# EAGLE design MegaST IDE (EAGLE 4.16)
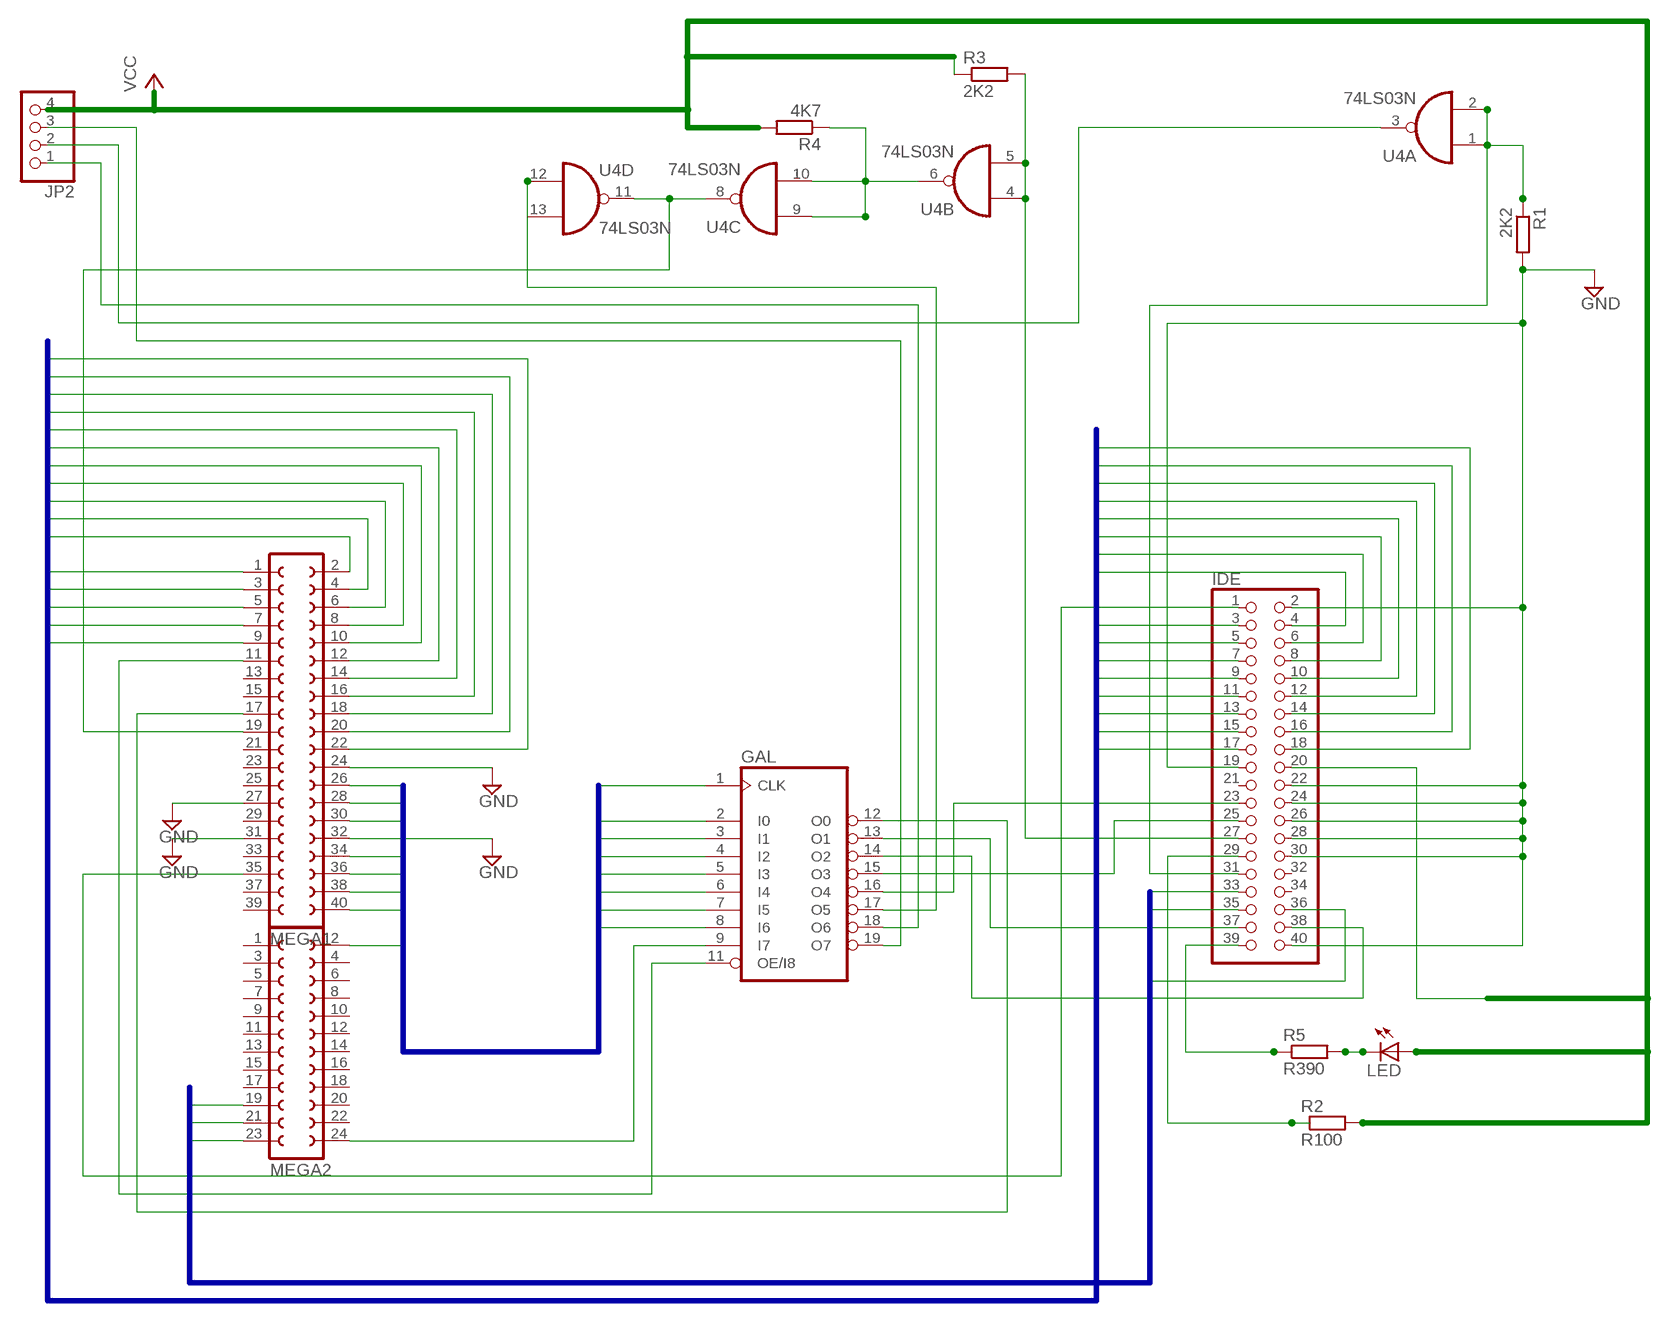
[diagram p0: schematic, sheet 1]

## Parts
GAL  16V8  [DIL20]
IDE  PINHD-2X20  [2X20]
JP2  PINHD-1X4  [1X04]
LED  LED3MM  [LED3MM]
MEGA1  FE20-2  [FE20-2]
MEGA2  FE12-2  [FE12-2]
R1  2K2  R-EU_0207/10  [0207/10]
R2  R100  R-EU_0207/10  [0207/10]
R3  2K2  R-EU_0207/10  [0207/10]
R4  4K7  R-EU_0207/10  [0207/10]
R5  R390  R-EU_0207/10  [0207/10]
U4  74LS03N  [DIL14]

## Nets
A2: IDE.35 MEGA2.19
A3: IDE.33 MEGA2.21
A4: IDE.36 MEGA2.23
A5: GAL.9(I7) MEGA2.24
A16: GAL.8(I6) MEGA2.2
A17: GAL.7(I5) MEGA1.40
A18: GAL.6(I4) MEGA1.38
A19: GAL.5(I3) MEGA1.36
A20: GAL.4(I2) MEGA1.34
A21: GAL.3(I1) MEGA1.30
A22: GAL.2(I0) MEGA1.28
A23: GAL.1(CLK) MEGA1.26
ACSI10: JP2.2 U4.3(A:O)
AS: GAL.11(OE/I8) MEGA1.11
CER: GAL.18(O6) JP2.1
D0: IDE.17 MEGA1.9
D1: IDE.15 MEGA1.7
D2: IDE.13 MEGA1.5
D3: IDE.11 MEGA1.3
D4: IDE.9 MEGA1.1
D5: IDE.7 MEGA1.2
D6: IDE.5 MEGA1.4
D7: IDE.3 MEGA1.6
D8: IDE.4 MEGA1.8
D9: IDE.6 MEGA1.10
D10: IDE.8 MEGA1.12
D11: IDE.10 MEGA1.14
D12: IDE.12 MEGA1.16
D13: IDE.14 MEGA1.18
D14: IDE.16 MEGA1.20
D15: IDE.18 MEGA1.22
DASP: IDE.39 R5.1
DMACK: IDE.29 R2.1
DTACK: MEGA1.19 U4.8(C:O) U4.11(D:O)
GND: IDE.2 IDE.19 IDE.22 IDE.24 IDE.26 IDE.28 IDE.30 IDE.40 MEGA1.24 MEGA1.27 MEGA1.31 MEGA1.32 R1.2
INTRQ: IDE.31 R1.1 U4.1(A:I0) U4.2(A:I1)
IORD: GAL.15(O3) IDE.25
IORDY: IDE.27 R3.2 U4.4(B:I0) U4.5(B:I1)
IOWR: GAL.16(O4) IDE.23
R5_LED: LED.K(C) R5.2
R/W: GAL.12(O0) MEGA1.17
RESET: IDE.1 MEGA1.35
ROM2: GAL.19(O7) JP2.3
SELP: GAL.13(O1) IDE.37
SELS: GAL.14(O2) IDE.38
U4_VCC1: R4.1 U4.6(B:O) U4.9(C:I0) U4.10(C:I1)
U4DTACK: GAL.17(O5) U4.12(D:I0) U4.13(D:I1)
VCC: IDE.20 JP2.4 LED.A R2.2 R3.1 R4.2
Unconnected: IDE.21 IDE.32 IDE.34 MEGA1.13 MEGA1.15 MEGA1.21 MEGA1.23 MEGA1.25 MEGA1.29 MEGA1.33 MEGA1.37 MEGA1.39 MEGA2.1 MEGA2.3 MEGA2.4 MEGA2.5 MEGA2.6 MEGA2.7 MEGA2.8 MEGA2.9 MEGA2.10 MEGA2.11 MEGA2.12 MEGA2.13 MEGA2.14 MEGA2.15 MEGA2.16 MEGA2.17 MEGA2.18 MEGA2.20 MEGA2.22

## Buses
A[16..23]
D[0..15]
A[2..4]

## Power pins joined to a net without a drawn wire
GND: GAL.10(GND) U4.7(P:GND)
VCC: GAL.20(VCC) U4.14(P:VCC)

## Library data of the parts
GAL = pal:16V8: PAL
IDE = pinhead:PINHD-2X20: PIN HEADER
JP2 = pinhead:PINHD-1X4: PIN HEADER
LED = led:LED: LED
MEGA1 = con-lsta:FE20-2: FEMALE HEADER
MEGA2 = con-lsta:FE12-2: FEMALE HEADER
R1-R5 = rcl:R-EU_: RESISTOR, European symbol
U4 = 74xx-eu:74*03: Quad 2-input NAND gate, open collector output

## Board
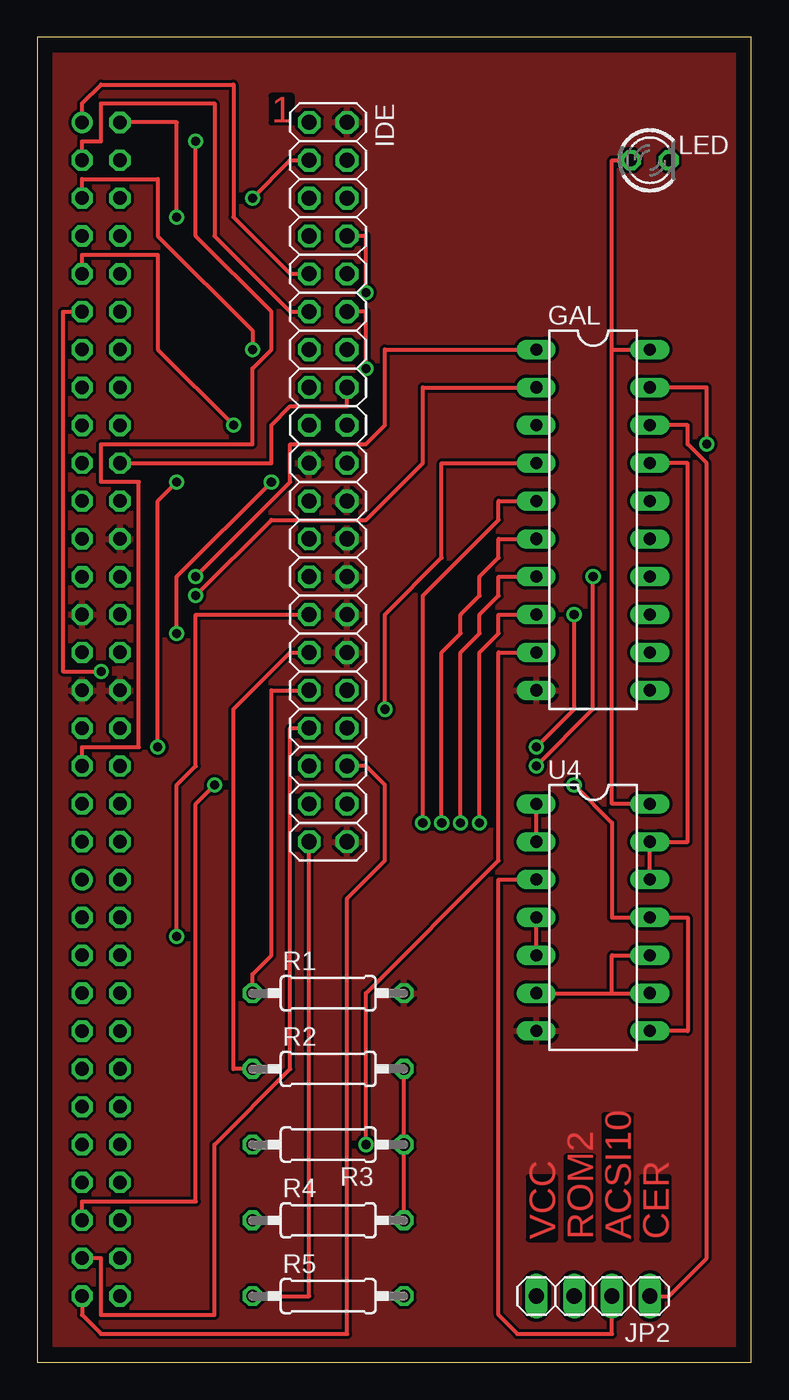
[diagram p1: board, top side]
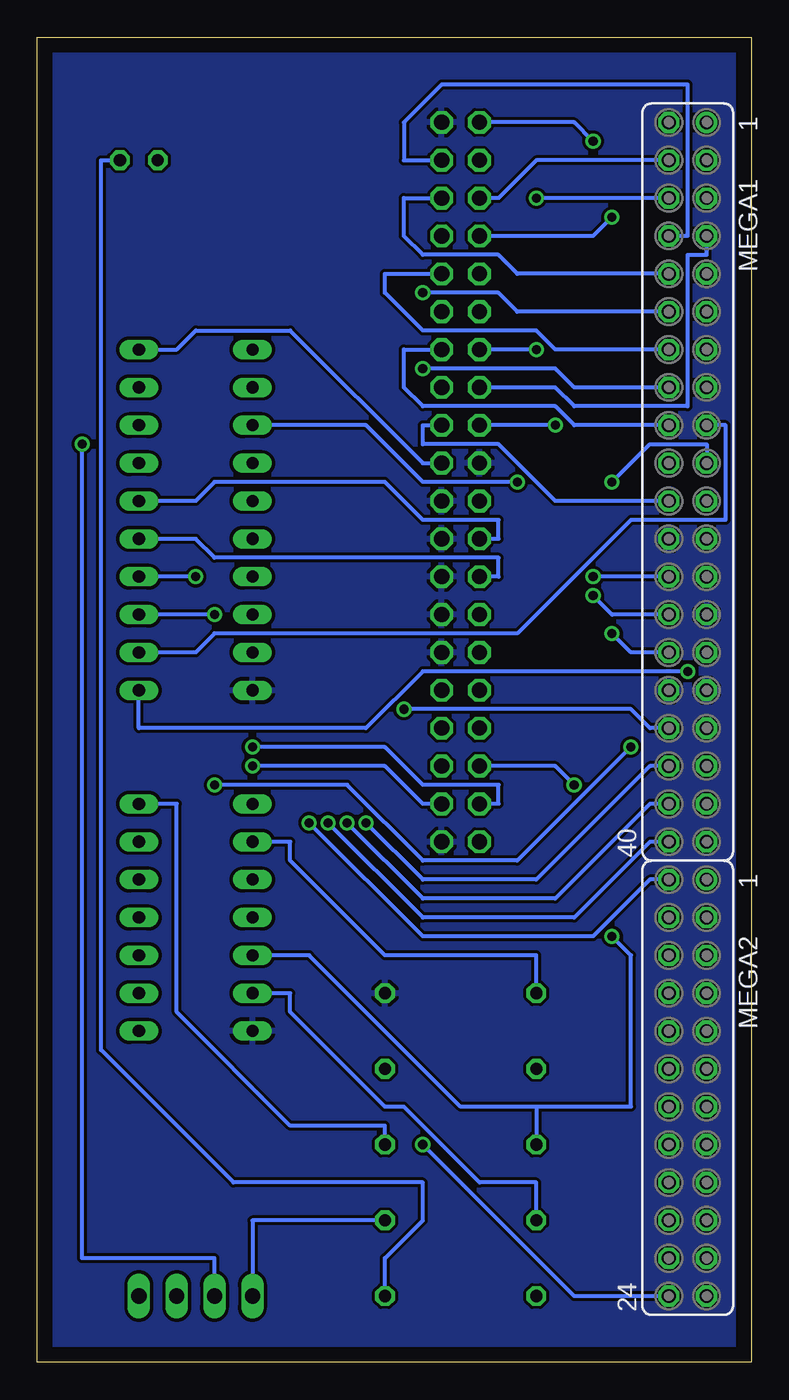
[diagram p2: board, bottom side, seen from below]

Size 47.93 x 88.89 mm. Coordinates in mm from the lower left corner, seen from the top.
Outline: 0,0 47.93,0 47.93,88.89 0,88.89 0,0
Copper layers (1*16): Top 0.035mm / dielectric 1.5mm / Bottom 0.035mm
Design rules "default": minimum track width 10mil, minimum drill 24mil, track to track 8mil, track to pad 8mil, pad to pad 8mil, via to via 8mil, smd to smd 8mil, copper to edge 40mil, drill to drill 8mil, minimum pad ring 10mil, minimum via ring 8mil, stop-mask expansion 4mil, vias tented up to drill 0mil, thermal gap 10mil

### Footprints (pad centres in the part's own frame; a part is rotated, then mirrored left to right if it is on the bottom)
DIL20 = drill 0.813 long: 1 -11.43,-3.81; 2 -8.89,-3.81; 3 -6.35,-3.81; 4 -3.81,-3.81; 5 -1.27,-3.81; 6 1.27,-3.81; 7 3.81,-3.81; 8 6.35,-3.81; 9 8.89,-3.81; 10 11.43,-3.81; 11 11.43,3.81; 12 8.89,3.81; 13 6.35,3.81; 14 3.81,3.81; 15 1.27,3.81; 16 -1.27,3.81; 17 -3.81,3.81; 18 -6.35,3.81; 19 -8.89,3.81; 20 -11.43,3.81
2X20 = drill 1.016 octagon: 1 -24.13,-1.27; 2 -24.13,1.27; 3 -21.59,-1.27; 4 -21.59,1.27; 5 -19.05,-1.27; 6 -19.05,1.27; 7 -16.51,-1.27; 8 -16.51,1.27; 9 -13.97,-1.27; 10 -13.97,1.27; 11 -11.43,-1.27; 12 -11.43,1.27; 13 -8.89,-1.27; 14 -8.89,1.27; 15 -6.35,-1.27; 16 -6.35,1.27; 17 -3.81,-1.27; 18 -3.81,1.27; 19 -1.27,-1.27; 20 -1.27,1.27; 21 1.27,-1.27; 22 1.27,1.27; 23 3.81,-1.27; 24 3.81,1.27; 25 6.35,-1.27; 26 6.35,1.27; 27 8.89,-1.27; 28 8.89,1.27; 29 11.43,-1.27; 30 11.43,1.27; 31 13.97,-1.27; 32 13.97,1.27; 33 16.51,-1.27; 34 16.51,1.27; 35 19.05,-1.27; 36 19.05,1.27; 37 21.59,-1.27; 38 21.59,1.27; 39 24.13,-1.27; 40 24.13,1.27
1X04 = drill 1.016 long: 1 -3.81,0; 2 -1.27,0; 3 1.27,0; 4 3.81,0
LED3MM = drill 0.813 octagon: A -1.27,0; K 1.27,0
FE20-2 = drill 0.914 round: 1 -24.13,1.27 | drill 0.914 octagon: 2 -24.13,-1.27; 3 -21.59,1.27; 4 -21.59,-1.27; 5 -19.05,1.27; 6 -19.05,-1.27; 7 -16.51,1.27; 8 -16.51,-1.27; 9 -13.97,1.27; 10 -13.97,-1.27; 11 -11.43,1.27; 12 -11.43,-1.27; 13 -8.89,1.27; 14 -8.89,-1.27; 15 -6.35,1.27; 16 -6.35,-1.27; 17 -3.81,1.27; 18 -3.81,-1.27; 19 -1.27,1.27; 20 -1.27,-1.27; 21 1.27,1.27; 22 1.27,-1.27; 23 3.81,1.27; 24 3.81,-1.27; 25 6.35,1.27; 26 6.35,-1.27; 27 8.89,1.27; 28 8.89,-1.27; 29 11.43,1.27; 30 11.43,-1.27; 31 13.97,1.27; 32 13.97,-1.27; 33 16.51,1.27; 34 16.51,-1.27; 35 19.05,1.27; 36 19.05,-1.27; 37 21.59,1.27; 38 21.59,-1.27; 39 24.13,1.27; 40 24.13,-1.27
FE12-2 = drill 0.914 round: 1 -13.97,1.27 | drill 0.914 octagon: 2 -13.97,-1.27; 3 -11.43,1.27; 4 -11.43,-1.27; 5 -8.89,1.27; 6 -8.89,-1.27; 7 -6.35,1.27; 8 -6.35,-1.27; 9 -3.81,1.27; 10 -3.81,-1.27; 11 -1.27,1.27; 12 -1.27,-1.27; 13 1.27,1.27; 14 1.27,-1.27; 15 3.81,1.27; 16 3.81,-1.27; 17 6.35,1.27; 18 6.35,-1.27; 19 8.89,1.27; 20 8.89,-1.27; 21 11.43,1.27; 22 11.43,-1.27; 23 13.97,1.27; 24 13.97,-1.27
0207/10 = drill 0.813 octagon: 1 -5.08,0; 2 5.08,0
DIL14 = drill 0.813 long: 1 -7.62,-3.81; 2 -5.08,-3.81; 3 -2.54,-3.81; 4 0,-3.81; 5 2.54,-3.81; 6 5.08,-3.81; 7 7.62,-3.81; 8 7.62,3.81; 9 5.08,3.81; 10 2.54,3.81; 11 0,3.81; 12 -2.54,3.81; 13 -5.08,3.81; 14 -7.62,3.81

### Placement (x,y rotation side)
GAL  37.3,56.51 270 top
IDE  19.52,59.05 270 top
JP2  37.3,4.44 180 top
LED  41.11,80.64 0 top
MEGA1  4.28,59.05 270 bottom
MEGA2  4.28,18.41 270 bottom
R1  19.52,24.76 0 top
R2  19.52,19.68 0 top
R3  19.52,14.6 180 top
R4  19.52,9.52 0 top
R5  19.52,4.44 0 top
U4  37.3,29.84 270 top

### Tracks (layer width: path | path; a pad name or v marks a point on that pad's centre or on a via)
A2  (via drill 0.61)
  Top 0.254: MEGA2.19 3.01,10.79 10.63,10.79 10.63,37.46 v11.9,38.73
  Bottom 0.254: v11.9,38.73 13.17,40 IDE.35
A3
  Top 0.254: MEGA2.21 4.28,6.98 4.28,3.17 11.9,3.17 11.9,14.6 16.98,19.68 16.98,42.54 IDE.33
A4
  Top 0.254: MEGA2.23 3.01,3.17 4.28,1.9 20.79,1.9 20.79,31.11 23.33,33.65 23.33,38.73 22.06,40 IDE.36
A5  (via drill 0.61)
  Top 0.254: v22.06,14.6 22.06,24.76 30.95,33.65 30.95,47.62 GAL.9
  Bottom 0.254: v22.06,14.6 11.9,4.44 MEGA2.24
A16  (via drill 0.61)
  Top 0.254: v29.68,36.19 29.68,47.62 30.95,48.89 30.95,50.16 GAL.8
  Bottom 0.254: v29.68,36.19 22.06,28.57 10.63,28.57 6.82,32.38 MEGA2.2
A17  (via drill 0.61)
  Top 0.254: v28.41,36.19 28.41,47.62 29.68,48.89 29.68,50.16 30.95,51.43 30.95,52.7 GAL.7
  Bottom 0.254: v28.41,36.19 22.06,29.84 11.9,29.84 6.82,34.92 MEGA1.40
A18  (via drill 0.61)
  Top 0.254: v27.14,36.19 27.14,47.62 28.41,48.89 28.41,50.16 29.68,51.43 29.68,52.7 30.95,53.97 30.95,55.24 GAL.6
  Bottom 0.254: v27.14,36.19 22.06,31.11 13.17,31.11 6.82,37.46 MEGA1.38
A19  (via drill 0.61)
  Top 0.254: v25.87,36.19 25.87,51.43 30.95,56.51 30.95,57.78 GAL.5
  Bottom 0.254: v25.87,36.19 22.06,32.38 14.44,32.38 6.82,40 MEGA1.36
A20  (via drill 0.61)
  Top 0.254: v23.33,43.81 23.33,50.16 27.14,53.97 27.14,60.32 GAL.4
  Bottom 0.254: v23.33,43.81 8.09,43.81 6.82,42.54 MEGA1.34
A21  (via drill 0.61)
  Top 0.254: v15.71,59.05 9.36,52.7 v9.36,48.89
  Bottom 0.254: v15.71,59.05 22.06,59.05 25.87,62.86 GAL.3 | v9.36,48.89 8.09,47.62 MEGA1.30
A22  (via drill 0.61)
  Top 0.254: v10.63,51.43 15.71,56.51 22.06,56.51 25.87,60.32 25.87,65.4 GAL.2
  Bottom 0.254: v10.63,51.43 9.36,50.16 MEGA1.28
A23  (via drill 0.61)
  Top 0.254: v10.63,52.7 16.98,59.05 16.98,61.59 22.06,61.59 23.33,62.86 23.33,67.94 GAL.1
  Bottom 0.254: MEGA1.26 v10.63,52.7
ACSI10
  Top 0.254: U4.3 30.95,32.38 30.95,3.17 32.22,1.9 38.57,1.9 JP2.2
AS  (via drill 0.61)
  Top 0.254: v4.28,46.35 1.74,46.35 1.74,70.48 MEGA1.11
  Bottom 0.254: GAL.11 41.11,42.54 25.87,42.54 22.06,46.35 v4.28,46.35
CER
  Top 0.254: JP2.1 42.38,4.44 44.92,6.98 44.92,60.32 43.65,61.59 43.65,62.86 GAL.18
D0  (via drill 0.61)
  Top 0.254: MEGA1.9 3.01,74.29 8.09,74.29 8.09,67.94 v13.17,62.86
  Bottom 0.254: v13.17,62.86 IDE.17
D1
  Bottom 0.254: MEGA1.7 3.01,74.29 4.28,74.29 4.28,64.13 11.9,64.13 13.17,65.4 IDE.15
D2  (via drill 0.61)
  Top 0.254: MEGA1.5 3.01,79.37 8.09,79.37 8.09,75.56 14.44,69.21 v14.44,67.94
  Bottom 0.254: v14.44,67.94 IDE.13
D3
  Top 0.254: MEGA1.3 3.01,81.91 4.28,81.91 4.28,84.45 11.9,84.45 11.9,75.56 16.98,70.48 IDE.11
D4
  Top 0.254: MEGA1.1 3.01,84.45 4.28,85.72 13.17,85.72 13.17,76.83 16.98,73.02 IDE.9
D5  (via drill 0.61)
  Top 0.254: MEGA1.2 9.36,83.18 v9.36,76.83
  Bottom 0.254: v9.36,76.83 10.63,75.56 IDE.7
D6
  Bottom 0.254: MEGA1.4 14.44,80.64 16.98,78.1 IDE.5
D7  (via drill 0.61)
  Top 0.254: v14.44,78.1 16.98,80.64 IDE.3
  Bottom 0.254: MEGA1.6 v14.44,78.1
D8
  Bottom 0.254: MEGA1.8 4.28,75.56 4.28,85.72 20.79,85.72 23.33,83.18 23.33,80.64 IDE.4
D9
  Bottom 0.254: MEGA1.10 15.71,73.02 16.98,74.29 22.06,74.29 23.33,75.56 23.33,78.1 IDE.6
D10  (via drill 0.61)
  Top 0.254: v22.06,71.75 22.06,75.56 IDE.8
  Bottom 0.254: MEGA1.12 15.71,70.48 16.98,71.75 v22.06,71.75
D11
  Bottom 0.254: MEGA1.14 13.17,67.94 14.44,69.21 22.06,69.21 24.6,71.75 24.6,73.02 IDE.10
D12  (via drill 0.61)
  Top 0.254: v22.06,66.67 22.06,70.48 IDE.12
  Bottom 0.254: MEGA1.16 11.9,65.4 13.17,66.67 v22.06,66.67
D13
  Bottom 0.254: MEGA1.18 11.9,62.86 13.17,64.13 22.06,64.13 23.33,65.4 23.33,67.94 IDE.14
D14
  Top 0.254: MEGA1.20 15.71,60.32 15.71,62.86 16.98,64.13 20.79,64.13 IDE.16
D15
  Bottom 0.254: MEGA1.22 13.17,57.78 16.98,61.59 22.06,61.59 22.06,62.86 IDE.18
DASP
  Top 0.254: R5.1 18.25,4.44 IDE.39
DMACK
  Top 0.254: R2.1 13.17,19.68 13.17,43.81 16.98,47.62 IDE.29
DTACK  (via drill 0.61)
  Top 0.254: U4.8 43.65,22.22 43.65,29.84 U4.11 38.57,29.84 38.57,36.19 v36.03,38.73 | v9.36,59.05 8.09,57.78 v8.09,41.27
  Bottom 0.254: MEGA1.19 3.01,61.59 6.82,61.59 v9.36,59.05 | v8.09,41.27 15.71,33.65 22.06,33.65 27.14,38.73 v36.03,38.73
GND
  pour Bottom: -0.8,88.26 48.73,88.26 48.73,0.63 -0.8,0.63
  pour Top: -0.8,88.26 48.73,88.26 48.73,0.63 -0.8,0.63
INTRQ
  Top 0.254: U4.2 U4.1 | IDE.31 15.71,45.08 15.71,27.3 14.44,26.03 R1.1
  Bottom 0.254: R1.1 14.44,27.3 24.6,27.3 30.95,33.65 30.95,34.92 U4.2
IORD
  Bottom 0.254: IDE.25 16.98,52.7 16.98,53.97 36.03,53.97 37.3,55.24 GAL.15
IORDY  (via drill 0.61)
  Top 0.254: U4.5 U4.4 | IDE.27 10.63,50.16 10.63,40 9.36,38.73 v9.36,28.57
  Bottom 0.254: 14.44,17.14 R3.2 | 14.44,17.14 19.52,17.14 29.68,27.3 U4.5 | v9.36,28.57 8.09,27.3 8.09,17.14 14.44,17.14
IOWR
  Bottom 0.254: IDE.23 16.98,55.24 16.98,56.51 22.06,56.51 24.6,59.05 36.03,59.05 37.3,57.78 GAL.16
R5_LED
  Bottom 0.254: R5.2 24.6,6.98 22.06,9.52 22.06,12.06 34.76,12.06 43.65,20.95 43.65,80.64 LED.K
R/W
  Bottom 0.254: MEGA1.17 1.74,62.86 1.74,56.51 8.09,56.51 15.71,48.89 36.03,48.89 37.3,47.62 GAL.12
RESET  (via drill 0.61)
  Top 0.254: MEGA1.35 3.01,41.27 6.82,41.27 6.82,59.05 4.28,59.05 4.28,61.59 14.44,61.59 14.44,66.67 15.71,67.94 15.71,70.48 10.63,75.56 v10.63,81.91
  Bottom 0.254: v10.63,81.91 11.9,83.18 IDE.1
ROM2  (via drill 0.61)
  Top 0.254: v44.92,61.59 44.92,65.4 GAL.19
  Bottom 0.254: v44.92,61.59 44.92,6.98 36.03,6.98 JP2.3
SELP  (via drill 0.61)
  Top 0.254: v36.03,50.16 36.03,43.81 v33.49,41.27
  Bottom 0.254: v33.49,41.27 24.6,41.27 22.06,38.73 16.98,38.73 16.98,37.46 IDE.37 | v36.03,50.16 GAL.13
SELS  (via drill 0.61)
  Top 0.254: v37.3,52.7 37.3,43.81 v33.49,40
  Bottom 0.254: v33.49,40 24.6,40 22.06,37.46 IDE.38 | v37.3,52.7 GAL.14
U4_VCC1
  Top 0.254: 38.57,24.76 U4.9 | U4.6 38.57,24.76 | 38.57,24.76 38.57,27.3 U4.10
  Bottom 0.254: R4.1 14.44,12.06 18.25,12.06 23.33,17.14 24.6,17.14 30.95,23.49 30.95,24.76 U4.6
U4DTACK
  Top 0.254: U4.12 U4.13 43.65,34.92 43.65,60.32 GAL.17
VCC
  Top 0.254: R4.2 R3.1 R2.2 | 38.57,67.94 38.57,37.46 U4.14 | 38.57,67.94 GAL.20 | LED.A 38.57,80.64 38.57,67.94
  Bottom 0.254: R4.2 33.49,9.52 JP2.4 | IDE.20 22.06,60.32 30.95,69.21 37.3,69.21 38.57,67.94 GAL.20 | R3.1 24.6,15.87 30.95,15.87 38.57,23.49 38.57,37.46 U4.14

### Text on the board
Top: 1 | VCC | ROM2 | ACSI10 | CER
